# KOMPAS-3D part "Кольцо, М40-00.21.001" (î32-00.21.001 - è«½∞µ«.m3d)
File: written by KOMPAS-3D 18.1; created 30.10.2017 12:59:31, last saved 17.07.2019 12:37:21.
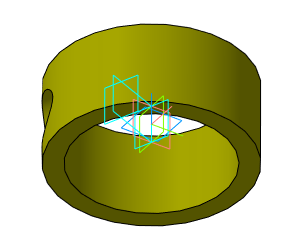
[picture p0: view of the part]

Document properties: Автор: Милов; Организация: Милов; Полное имя файла: D:\Magna\Магна Ins\Магна ins 32\М32-00.21.001 - Кольцо.m3d

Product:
- Part/product: Кольцо  | designation М40-00.21.001
    Материал: Полипропилен  ГОСТ 26996-86 (density 900 kg/m3)
    Масса: 1.59002
    Раздел спецификации: Детали
    Форматы листов документа: A3
    source file: ..\Магна ins 40\3Д\М40-00.21.001 - Кольцо.cdw
- Part/product: Кольцо  | designation М32-00.21.001
    Материал: Полипропилен  ГОСТ 26996-86 (density 900 kg/m3)
    Масса: 1.66598
    source file: М32-00.21.001 - Кольцо.cdw
- Part/product: Кольцо  | designation М32-00.21.001
    Материал: Полипропилен  ГОСТ 26996-86 (density 900 kg/m3)
    Масса: 1.57813
  - Body: Тело 1
      Материал: Полипропилен  ГОСТ 26996-86 (density 0.9 kg/m3)
  - Body: Тело 6
      Материал: Полипропилен  ГОСТ 26996-86 (density 0.9 kg/m3)

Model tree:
1. Эскиз:1
2. Операция выдавливания:6
     Расстояние 1 = 105; Расстояние 2 = 39; На расстояние 2 = 15
3. Плоскость под углом:1
     Угол = 22
4. Смещенная плоскость:1
     Расстояние = 60
5. Плоскость под углом:4
     Угол = 90
6. Эскиз:12
7. Вырезать элемент выдавливания:4
     Расстояние 2 = 163.628
8. Плоскость под углом:5
     Угол = -68
9. Эскиз:30
10. Вырезать элемент выдавливания:7
     Расстояние 1 = 137.433
11. Условное изображение резьбы:1  (with: Вырезать элемент выдавливания:7)  (labels: M8; cil0_24705-2004 coarse)
     Длина резьбы = 25.08; Шаг резьбы = 1.25; Номинальный диаметр резьбы = 8
12. Подгонка:1  (with: Вырезать элемент выдавливания:7)
13. Условное изображение резьбы:2  (with: Вырезать элемент выдавливания:7)  (labels: M8; cil0_24705-2004 coarse)
     Длина резьбы = 25.08; Шаг резьбы = 1.25; Номинальный диаметр резьбы = 8
14. Подгонка:2  (with: Вырезать элемент выдавливания:7)
15. Массив по концентрической сетке:2  (with: Вырезать элемент выдавливания:7, Плоскость под углом:5, Эскиз:30)  (labels: Полипропилен  ГОСТ 26996-86; C:\Users\Kon\Desktop\Горизонтальный насос Лифлянд\Макет.a3d)  (4 pattern instances)
     Шаг 2 = 360
16. Эскиз:34
17. Вырезать элемент выдавливания:9  (labels: Полипропилен  ГОСТ 26996-86; М32-00.21.000 - Кольцо.a3d)
     Расстояние 1 = 30
18. Вырезать элемент выдавливания:12
     Расстояние 1 = 134
19. Изменение положения:1
20. Изменение положения:2
21. Изменение положения:3
22. Элемент выдавливания:1  (with: Изменение положения:3)  (labels: Полипропилен  ГОСТ 26996-86)
     Расстояние 2 = 3

Referenced files in D:\Magna\Магна Ins\Магна ins 32\: М32-00.21.000 - Кольцо.a3d
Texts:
  Корпус\Кольцо\Труба ф63х5.8 (PN10) FV PPR ф. FV PLAST

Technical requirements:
  Gost Type A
